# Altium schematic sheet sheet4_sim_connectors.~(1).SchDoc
size A3; SheetNumber: 3; SheetTotal: 4
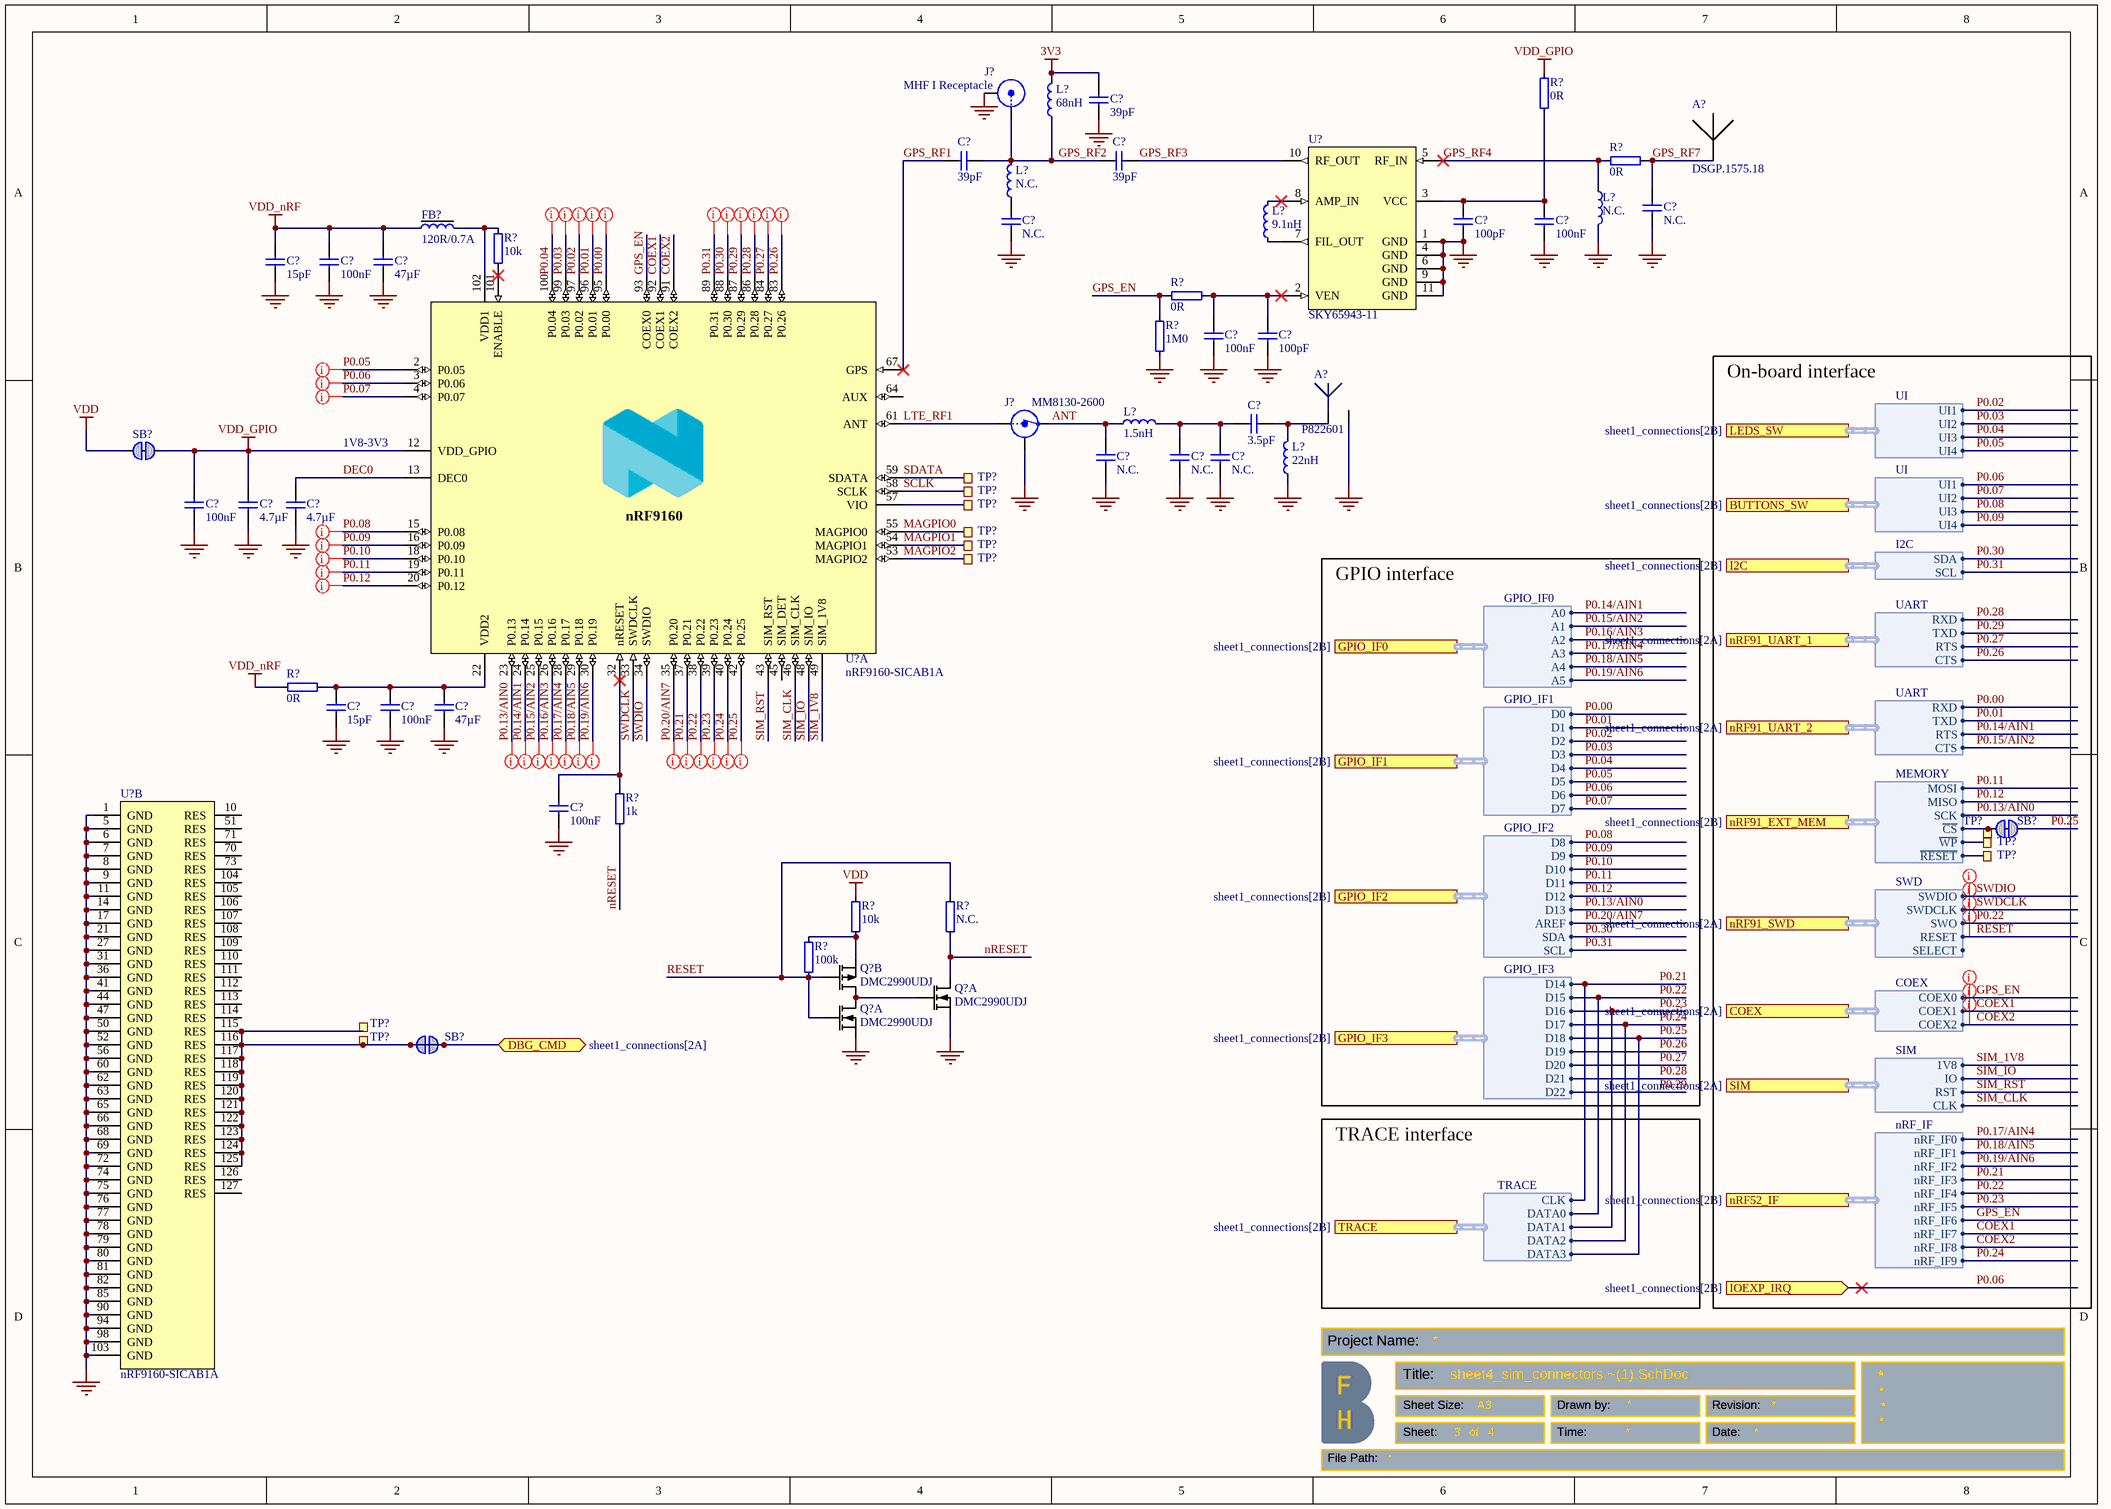
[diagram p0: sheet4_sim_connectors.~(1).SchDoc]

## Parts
(Parts that share a designator on the sheet are numbered #1, #2 ... from top to bottom, then left to right.)
A?#1  DSGP.1575.18  [DSGP.1575.18]
A?#2  P822601  [P822601]
C?#1  39pF  [CAPC0603X03L_C]
C?#2  39pF  [CAPC0603X03L_C]
C?#3  39pF  [CAPC0603X03L_C]
C?#4  N.C.  [CAPC1005X04L_NC]
C?#5  15pF  [CAPC0603X03L_C]
C?#6  100nF  [CAPC0603X03L_C]
C?#7  47µF  [CAPC2012X11L]
C?#8  N.C.  [CAPC0603X03L_C_NC]
C?#9  100pF  [CAPC0603X03L_C]
C?#10  100nF  [CAPC0603X03L_C]
C?#11  100nF  [CAPC0603X03L_C]
C?#12  100pF  [CAPC0603X03L_C]
C?#13  3.5pF  [CAPC0603X03L_C]
C?#14  N.C.  [CAPC0603X03L_C_NC]
C?#15  N.C.  [CAPC0603X03L_C_NC]
C?#16  N.C.  [CAPC0603X03L_C_NC]
C?#17  100nF  [CAPC0603X03L_C]
C?#18  4.7µF  [CAPC1005X04L]
C?#19  4.7µF  [CAPC2012X11L]
C?#20  15pF  [CAPC0603X03L_C]
C?#21  100nF  [CAPC0603X03L_C]
C?#22  47µF  [CAPC2012X11L]
C?#23  100nF  [CAPC0603X03L_C]
FB?  120R/0.7A  [INDC1005X04L]
J?#1  MHF I Receptacle  [COAXIAL RF U.FL-R-SMT-1]
J?#2  MM8130-2600  [COAXIAL-SWF]
L?#1  68nH  [INDC1005X04L_WW]
L?#2  N.C.  [INDC1005X04L_NC]
L?#3  N.C.  [INDC1005X04L_NC]
L?#4  9.1nH  [INDC1005X04L_WW]
L?#5  1.5nH  [INDC0603X03L_C]
L?#6  22nH  [INDC0603X03L_C]
Q?#1  DMC2990UDJ  [SOTFL35P100X50-6N]  (part B of 2)
Q?#2  DMC2990UDJ  [SOTFL35P100X50-6N]  (part A of 2)
Q?#3  DMC2990UDJ  [SOTFL35P100X50-6N]  (part A of 2)
R?#1  0R  [RESC0603X03L_C]
R?#2  0R  [RESC1005X04L]
R?#3  10k  [RESC0603X03L_C]
R?#4  0R  [RESC0603X03L_C]
R?#5  1M0  [RESC0603X03L_C]
R?#6  0R  [RESC0603X03L_C]
R?#7  1k  [RESC0603X03L_C]
R?#8  10k  [RESC0603X03L_C]
R?#9  N.C.  [RESC0603X03L_C_NC]
R?#10  100k  [RESC0603X03L_C]
SB?#1  Solderbridge  [Solderbridge_Shorted]  (value not drawn)  (net tie, no BOM)
SB?#2  Solderbridge  [Solderbridge_Shorted]  (value not drawn)  (net tie, no BOM)
SB?#3  Solderbridge  [Solderbridge]  (value not drawn)  (no BOM)
TP?#1  Ø1.0mm,SMD  [TP_SMD_D1.0mm]  (value not drawn)  (no BOM)
TP?#2  Ø1.0mm,SMD  [TP_SMD_D1.0mm]  (value not drawn)  (no BOM)
TP?#3  Ø1.0mm,SMD  [TP_SMD_D1.0mm]  (value not drawn)  (no BOM)
TP?#4  Ø1.0mm,SMD  [TP_SMD_D1.0mm]  (value not drawn)  (no BOM)
TP?#5  Ø1.0mm,SMD  [TP_SMD_D1.0mm]  (value not drawn)  (no BOM)
TP?#6  Ø1.0mm,SMD  [TP_SMD_D1.0mm]  (value not drawn)  (no BOM)
TP?#7  Ø1.5mm,SMD  [TP_SMD_D1.5mm]  (value not drawn)  (no BOM)
TP?#8  Ø1.5mm,SMD  [TP_SMD_D1.5mm]  (value not drawn)  (no BOM)
TP?#9  Ø1.5mm,SMD  [TP_SMD_D1.5mm]  (value not drawn)  (no BOM)
TP?#10  Ø1.0mm,SMD  [TP_SMD_D1.0mm]  (value not drawn)  (no BOM)
TP?#11  Ø1.0mm,SMD  [TP_SMD_D1.0mm]  (value not drawn)  (no BOM)
U?#1  SKY65943-11  [SKY65943-11]
U?#2  nRF9160-SICAB1A  [LGA50P1600X1050X104-161N]  (part A of 2)
U?#3  nRF9160-SICAB1A  [LGA50P1600X1050X104-161N]  (part B of 2)

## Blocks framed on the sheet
On-board interface: SB?#2 TP?#7-TP?#9

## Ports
BUTTONS_SW (harness UI, see sheet1_connections[2B]), COEX (harness COEX, see sheet1_connections[2A]), DBG_CMD (bidir, see sheet1_connections[2A]), GPIO_IF0 (harness GPIO_IF0, see sheet1_connections[2B]), GPIO_IF1 (harness GPIO_IF1, see sheet1_connections[2B]), GPIO_IF2 (harness GPIO_IF2, see sheet1_connections[2B]), GPIO_IF3 (harness GPIO_IF3, see sheet1_connections[2B]), I2C (harness I2C, see sheet1_connections[2B]), IOEXP_IRQ (in, see sheet1_connections[2B]), LEDS_SW (harness UI, see sheet1_connections[2B]), nRF52_IF (harness nRF_IF, see sheet1_connections[2B]), nRF91_EXT_MEM (harness MEMORY, see sheet1_connections[2B]), nRF91_SWD (harness SWD, see sheet1_connections[2A]), nRF91_UART_1 (harness UART, see sheet1_connections[2A]), nRF91_UART_2 (harness UART, see sheet1_connections[2A]), SIM (harness SIM, see sheet1_connections[2A]), TRACE (harness TRACE, see sheet1_connections[2B])

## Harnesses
COEX: COEX0, COEX2, COEX1
UART: RTS, CTS, RXD, TXD
SIM: CLK, IO, 1V8, RST
SWD: SWDIO, SWDCLK, SWO, RESET, SELECT
I2C: SCL, SDA
GPIO_IF1: D0, D1, D2, D3, D4, D5, D6, D7
GPIO_IF2: D8, D9, D10, D11, D12, D13, AREF, SDA, SCL
GPIO_IF0: A0, A1, A2, A3, A4, A5
GPIO_IF3: D14, D15, D16, D17, D18, D19, D20, D21, D22
TRACE: CLK, DATA0, DATA1, DATA3, DATA2
UI: UI4, UI3, UI2, UI1
nRF_IF: nRF_IF0, nRF_IF1, nRF_IF2, nRF_IF3, nRF_IF4, nRF_IF5, nRF_IF6, nRF_IF7, nRF_IF8, nRF_IF9
MEMORY: SCK, ~{CS}, MOSI, MISO, ~{WP}, ~{RESET}

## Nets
3V3: C?#1.2 L?#1.1
GND: A?#1.2(GND) A?#2.2 C?#1.1 C?#4.2 C?#5.2 C?#6.2 C?#7.2 C?#8.1 C?#9.1 C?#10.1 C?#11.1 C?#12.1 C?#14.1 C?#15.1 C?#16.1 C?#17.2 C?#18.2 C?#19.2 C?#20.2 C?#21.2 C?#22.2 C?#23.2 J?#1.2(Y) J?#2.2(Shield) L?#3.2 L?#6.1 Q?#2.1(S1) Q?#3.1(S1) R?#5.1 U?#1.1(GND) U?#1.4(GND) U?#1.6(GND) U?#1.9(GND) U?#1.11(GND) U?#3.1(GND) U?#3.5(GND) U?#3.6(GND) U?#3.7(GND) U?#3.8(GND) U?#3.9(GND) U?#3.11(GND) U?#3.14(GND) U?#3.17(GND) U?#3.21(GND) U?#3.27(GND) U?#3.31(GND) U?#3.36(GND) U?#3.41(GND) U?#3.44(GND) U?#3.47(GND) U?#3.50(GND) U?#3.52(GND) U?#3.56(GND) U?#3.60(GND) U?#3.62(GND) U?#3.63(GND) U?#3.65(GND) U?#3.66(GND) U?#3.68(GND) U?#3.69(GND) U?#3.72(GND) U?#3.74(GND) U?#3.75(GND) U?#3.76(GND) U?#3.77(GND) U?#3.78(GND) U?#3.79(GND) U?#3.80(GND) U?#3.81(GND) U?#3.82(GND) U?#3.85(GND) U?#3.90(GND) U?#3.94(GND) U?#3.98(GND) U?#3.103(GND)
VDD: R?#8.1 SB?#1.1
VDD_GPIO: C?#17.1 C?#18.1 R?#1.2 SB?#1.2 U?#2.12(VDD_GPIO)
VDD_nRF: C?#5.1 C?#6.1 C?#7.1 FB?.1 R?#6.1
ANT: C?#14.2 J?#2.3(OUT) L?#5.1
COEX1: U?#2.92(COEX1) ; port COEX.COEX1, port nRF52_IF.nRF_IF7
COEX2: U?#2.91(COEX2) ; port COEX.COEX2, port nRF52_IF.nRF_IF8
DBG_CMD: SB?#3.1 SB?#3.2 TP?#10.1 TP?#11.1 U?#3.115(RES) U?#3.116(RES) U?#3.117(RES) U?#3.118(RES) U?#3.119(RES) U?#3.120(RES) U?#3.121(RES) U?#3.122(RES) U?#3.123(RES) U?#3.124(RES) U?#3.125(RES) ; port DBG_CMD
DEC0: C?#19.1 U?#2.13(DEC0)
GPS_EN: R?#4.1 R?#5.2 U?#2.93(COEX0) ; port COEX.COEX0, port nRF52_IF.nRF_IF6
GPS_RF1: C?#2.2 U?#2.67(GPS)
GPS_RF2: C?#2.1 C?#3.2 J?#1.1(X) L?#1.2 L?#2.1
GPS_RF3: C?#3.1 U?#1.10(RF_OUT)
GPS_RF4: L?#3.1 R?#2.1 U?#1.5(RF_IN)
GPS_RF7: A?#1.1 C?#4.1 R?#2.2
LTE_RF1: J?#2.1(IN) U?#2.61(ANT)
MAGPIO0: TP?#4.1 U?#2.55(MAGPIO0)
MAGPIO1: TP?#5.1 U?#2.54(MAGPIO1)
MAGPIO2: TP?#6.1 U?#2.53(MAGPIO2)
nRESET: Q?#2.6(D1) R?#7.1 R?#9.2
P0.00: U?#2.95(P0.00) ; port nRF91_UART_2.RXD, port GPIO_IF1.D0
P0.01: U?#2.96(P0.01) ; port nRF91_UART_2.TXD, port GPIO_IF1.D1
P0.02: U?#2.97(P0.02) ; port GPIO_IF1.D2, port LEDS_SW.UI1
P0.03: U?#2.99(P0.03) ; port GPIO_IF1.D3, port LEDS_SW.UI2
P0.04: U?#2.100(P0.04) ; port GPIO_IF1.D4, port LEDS_SW.UI3
P0.05: U?#2.2(P0.05) ; port GPIO_IF1.D5, port LEDS_SW.UI4
P0.06: U?#2.3(P0.06) ; port IOEXP_IRQ, port GPIO_IF1.D6, port BUTTONS_SW.UI1
P0.07: U?#2.4(P0.07) ; port GPIO_IF1.D7, port BUTTONS_SW.UI2
P0.08: U?#2.15(P0.08) ; port GPIO_IF2.D8, port BUTTONS_SW.UI3
P0.09: U?#2.16(P0.09) ; port GPIO_IF2.D9, port BUTTONS_SW.UI4
P0.10: U?#2.18(P0.10) ; port GPIO_IF2.D10
P0.11: U?#2.19(P0.11) ; port GPIO_IF2.D11, port nRF91_EXT_MEM.MOSI
P0.12: U?#2.20(P0.12) ; port GPIO_IF2.D12, port nRF91_EXT_MEM.MISO
P0.13/AIN0: U?#2.23(P0.13) ; port GPIO_IF2.D13, port nRF91_EXT_MEM.SCK
P0.14/AIN1: U?#2.24(P0.14) ; port nRF91_UART_2.RTS, port GPIO_IF0.A0
P0.15/AIN2: U?#2.25(P0.15) ; port nRF91_UART_2.CTS, port GPIO_IF0.A1
P0.16/AIN3: U?#2.26(P0.16) ; port GPIO_IF0.A2
P0.17/AIN4: U?#2.28(P0.17) ; port GPIO_IF0.A3, port nRF52_IF.nRF_IF0
P0.18/AIN5: U?#2.29(P0.18) ; port GPIO_IF0.A4, port nRF52_IF.nRF_IF1
P0.19/AIN6: U?#2.30(P0.19) ; port GPIO_IF0.A5, port nRF52_IF.nRF_IF2
P0.20/AIN7: U?#2.35(P0.20) ; port GPIO_IF2.AREF
P0.21: U?#2.37(P0.21) ; port GPIO_IF3.D14, port TRACE.CLK, port nRF52_IF.nRF_IF3
P0.22: U?#2.38(P0.22) ; port nRF91_SWD.SWO, port GPIO_IF3.D15, port TRACE.DATA0, port nRF52_IF.nRF_IF4
P0.23: U?#2.39(P0.23) ; port GPIO_IF3.D16, port TRACE.DATA1, port nRF52_IF.nRF_IF5
P0.24: U?#2.40(P0.24) ; port GPIO_IF3.D17, port TRACE.DATA2, port nRF52_IF.nRF_IF9
P0.25: SB?#2.1 U?#2.42(P0.25) ; port GPIO_IF3.D18, port TRACE.DATA3
P0.26: U?#2.83(P0.26) ; port nRF91_UART_1.CTS, port GPIO_IF3.D19
P0.27: U?#2.84(P0.27) ; port nRF91_UART_1.RTS, port GPIO_IF3.D20
P0.28: U?#2.86(P0.28) ; port nRF91_UART_1.RXD, port GPIO_IF3.D21
P0.29: U?#2.87(P0.29) ; port nRF91_UART_1.TXD, port GPIO_IF3.D22
P0.30: U?#2.88(P0.30) ; port I2C.SDA, port GPIO_IF2.SDA
P0.31: U?#2.89(P0.31) ; port I2C.SCL, port GPIO_IF2.SCL
RESET: Q?#1.5(G2) Q?#3.2(G1) R?#9.1 R?#10.1 ; port nRF91_SWD.RESET
SCLK: TP?#2.1 U?#2.58(SCLK)
SDATA: TP?#1.1 U?#2.59(SDATA)
SIM_1V8: U?#2.49(SIM_1V8) ; port SIM.1V8
SIM_CLK: U?#2.46(SIM_CLK) ; port SIM.CLK
SIM_IO: U?#2.48(SIM_IO) ; port SIM.IO
SIM_RST: U?#2.43(SIM_RST) ; port SIM.RST
SWDCLK: U?#2.33(SWDCLK) ; port nRF91_SWD.SWDCLK
SWDIO: U?#2.34(SWDIO) ; port nRF91_SWD.SWDIO
NetA?#2_1: A?#2.1 C?#13.2 L?#6.2
NetC?#8_2: C?#8.2 L?#2.2
NetC?#9_2: C?#9.2 C?#10.2 R?#1.1 U?#1.3(VCC)
NetC?#11_2: C?#11.2 C?#12.2 R?#4.2 U?#1.2(VEN)
NetC?#13_1: C?#13.1 C?#15.2 C?#16.2 L?#5.2
NetC?#20_1: C?#20.1 C?#21.1 C?#22.1 R?#6.2 U?#2.22(VDD2)
NetC?#23_1: C?#23.1 R?#7.2 U?#2.32(nRESET)
NetFB?_2: FB?.2 R?#3.1 U?#2.102(VDD1)
NetL?#4_1: L?#4.1 U?#1.8(AMP_IN)
NetL?#4_2: L?#4.2 U?#1.7(FIL_OUT)
NetQ?#1_3: Q?#1.3(D2) Q?#2.2(G1) Q?#3.6(D1)
NetQ?#1_4: Q?#1.4(S2) R?#8.2 R?#10.2
NetR?#3_2: R?#3.2 U?#2.101(ENABLE)
NetSB?#2_2: SB?#2.2 TP?#7.1 ; port nRF91_EXT_MEM.~{CS}
NetTP?#3_1: TP?#3.1 U?#2.57(VIO)
NetTP?#8_1: TP?#8.1 ; port nRF91_EXT_MEM.~{WP}
NetTP?#9_1: TP?#9.1 ; port nRF91_EXT_MEM.~{RESET}

Not connected (* = marked no-connect by the designer): U?#2 45(SIM_DET) 64(AUX); U?#3 10(RES) 51(RES) 70(RES) 71(RES) 73(RES) 104(RES) 105(RES) 106(RES) 107(RES) 108(RES) 109(RES) 110(RES) 111(RES) 112(RES) 113(RES) 114(RES) 126(RES) 127(RES)

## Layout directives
net class GPIO: P0.00, P0.01, P0.02, P0.03, P0.04, P0.05, P0.06, P0.07, P0.08, P0.09, P0.10, P0.11, P0.12, P0.13/AIN0, P0.14/AIN1, P0.15/AIN2, P0.16/AIN3, P0.17/AIN4, P0.18/AIN5, P0.19/AIN6, P0.20/AIN7, P0.21, P0.22, P0.23, P0.24, P0.25, P0.26, P0.27, P0.28, P0.29, P0.30, P0.31
net class SWD: P0.22, RESET, SWDCLK, SWDIO
net class COEX: COEX1, COEX2, GPS_EN

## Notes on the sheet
- 1V8-3V3
- GPIO interface
- TRACE interface

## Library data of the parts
A?#1 = DSGP.1575.18.4.A.02: 18 x 18 mm Low Profile GPS L1 / GALILEO E1 Passive Patch Antenna; Manufacturer: Taoglas; Part number IPS: 00000004435; Note: N.A.; Pad Count: 2
A?#2 = P822601: ANTENNA PRESTTA OCTABAND LTE; Manufacturer: Ethertronics; Part number IPS: 00000009001; Note: N.A.; Pad Count: 2
C?#1-C?#3 = C0201-39p: Capacitor, NP0, ±1%, 25V; Manufacturer: Murata; Manufacturer Part Number: GRM0335C1E390FA01; Part number IPS: 00000001668; Artikkelnr Noca: N.A.; Pad Count: 2
C?#4 = C0402-N.C.: Not mounted; Manufacturer: N.A.; Assembly: Not mounted; Note: Chip Cap; Pad Count: 2
C?#5 C?#20 = C0201-15p: Capacitor, NP0, ±5%, 25V; Manufacturer: Murata; Manufacturer Part Number: GRM0335C1E150JD03D; Part number IPS: 00000003193; Artikkelnr Noca: N.A.; Pad Count: 2
C?#6 C?#10 C?#11 C?#17 C?#21 C?#23 = C0201-100n: Capacitor, X5R, ±10%; Manufacturer: N.A.; Part number IPS: 00000001248, 00000002505; Note: 16V; Pad Count: 2
C?#7 C?#22 = C0805-47µ-10V: Capacitor, X5R, ±20%, 10V; Manufacturer: Murata; Manufacturer Part Number: GRM21BR61A476ME15; Part number IPS: 00000004759; Artikkelnr Noca: N.A.; Pad Count: 2
C?#8 = C0201-N.C.: Not mounted; Manufacturer: N.A.; Assembly: Not mounted; Note: Chip Cap; Pad Count: 2
C?#9 C?#12 = C0201-100p: Capacitor, NP0, ±2%, 25V; Manufacturer: Murata; Manufacturer Part Number: GRM0335C1E101GA01; Part number IPS: 00000007853; Artikkelnr Noca: N.A.; Pad Count: 2
C?#13 = C0201-3.5p: Capacitor, NP0, ±0.1pF, 25V; Manufacturer: Murata; Manufacturer Part Number: GJM0335C1H3R5BB01E; Part number IPS: 00000001469; Artikkelnr Noca: N.A.; Pad Count: 2
C?#14-C?#16 = C0201-N.C.: Not mounted; Manufacturer: N.A.; Note: Chip Cap; Assembly: Not mounted; Pad Count: 2
C?#18 = C0402-4µ7: Capacitor, X5R, ±20%; Manufacturer: N.A.; Part number IPS: 00000001251, 00000007165; Note: 10V; Artikkelnr Noca: 20039482; Pad Count: 2
C?#19 = C0805-4µ7: Capacitor, X5R, ±10%, 16V; Manufacturer: N.A.; Part number IPS: 00000006289; Artikkelnr Noca: 20039266; Pad Count: 2
FB? = FB0402-120R@100M-700mA: Ferrite Bead, 120 Ohm @ 100MHz, 700mA, 130 mOhm Max; Manufacturer: Murata; Manufacturer Part Number: BLM15AX121SN1; Part number IPS: 00000004487; Note: N.A.; Pad Count: 2
J?#1 = 20279-001E-03: Ultraminiature Coaxial Connector, 50 Ohm, SMD; Manufacturer: Wellshow; Part number IPS: 00000004436; Note: N.A.; Pad Count: 3
J?#2 = MM8130-2600: Coaxial Connector with Switch; Manufacturer: Murata; Part number IPS: 00000009955; Note: N.A.; Artikkelnr Noca: 55029011; Pad Count: 3
L?#1 = L0402-68n-Wirewound-Murata: Inductor, 140mA, ±2%, 1960mΩ, Q=20; Manufacturer: Murata; Manufacturer Part Number: LQW15AN68NG00; Part number IPS: 00000002494; Note: -55°C ~ 125°C; Artikkelnr Noca: N.A.; Pad Count: 2
L?#2 L?#3 = L0402-N.C.: Not mounted; Manufacturer: N.A.; Assembly: Not mounted; Pad Count: 2
L?#4 = L0402-9n1-Wirewound-Murata: Inductor, 540mA, ±2%, 140mΩ, Q=25; Manufacturer: Murata; Manufacturer Part Number: LQW15AN9N1G00; Part number IPS: 00000002497; Note: -55°C ~ 125°C; Artikkelnr Noca: N.A.; Pad Count: 2
L?#5 = L0201-1n5: Inductor, 650mA, ±0.1nH; Manufacturer: Murata; Manufacturer Part Number: LQP03TQ1N5B02D; Part number IPS: 00000000836; Note: N.A.; Pad Count: 2
L?#6 = L0201-22n: Chip Inductor; Manufacturer: N.A.; Part number IPS: 00000001478; Note: High frequency chip inductor ±10%; Pad Count: 2
Q?#1-Q?#3 = DMC2990UDJ-7: MOSFET, Dual N and P-Channel, 20V, 450mA/310mA, 990mOhm, 350mW; Manufacturer: Diodes Incorporated; Part number IPS: 00000004489; Note: N.A.; Pad Count: 6
R?#1 R?#4 R?#6 = R0201-0R: Resistor, ±5%, 0.05W; Manufacturer: N.A.; Part number IPS: 00000003245; Note: Chip Res 5%; Pad Count: 2
R?#2 = R0402-0R: Resistor, ±5%, 0.063W; Manufacturer: N.A.; Part number IPS: 00000007128; Note: Chip Res 5%; Artikkelnr Noca: 27049000; Pad Count: 2
R?#3 R?#8 = R0201-10k: Resistor, ±1%, 0.05W; Manufacturer: N.A.; Part number IPS: 00000001255; Note: Chip Res 1%; Pad Count: 2
R?#5 = R0201-1M0: Resistor, ±1%, 0.05W; Manufacturer: N.A.; Part number IPS: 00000001418; Note: Chip Res 1%; Pad Count: 2
R?#7 = R0201-1k0: Resistor, ±1%, 0.05W; Manufacturer: N.A.; Part number IPS: 00000005786; Note: Chip Res 1%; Pad Count: 2
R?#9 = R0201-N.C.: Not mounted; Manufacturer: N.A.; Note: Chip Res; Assembly: Not mounted; Pad Count: 2
R?#10 = R0201-100k: Resistor, ±1%, 0.05W; Manufacturer: N.A.; Part number IPS: 00000001419; Note: Chip Res 1%; Pad Count: 2
SB?#1 SB?#2 = Solderbridge Shorted: Shorted Solderbridge; Manufacturer: N.A.; Pad Count: 2
SB?#3 = Solderbridge: Manufacturer: N.A.; Pad Count: 2
TP?#1-TP?#6 TP?#10 TP?#11 = TP_SMD_Ø1.0MM: 1.0mm circular SMD testpad; Manufacturer: Nordic Semiconductor; Manufacturer Part Number: N.A.; Pad Count: 1
TP?#7-TP?#9 = TP_SMD_Ø1.5MM: 1.5mm circular SMD testpad; Manufacturer: Nordic Semiconductor; Manufacturer Part Number: N.A.; Pad Count: 1
U?#1 = SKY65943-11: GNSS Low-Noise Amplifier Front-End Module with Integrated Pre-Filter and Post-Filter; Manufacturer: Skyworks; Part number IPS: 00000002997; Note: N.A.; Pad Count: 10
U?#2 U?#3 = nRF9160-SICAB1A: Low power System-in-Package with integrated LTE-M/NB-IoT modem and GPS; Manufacturer: Nordic Semiconductor; Part number IPS: 80000002329; Note: N.A.; Pad Count: 161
